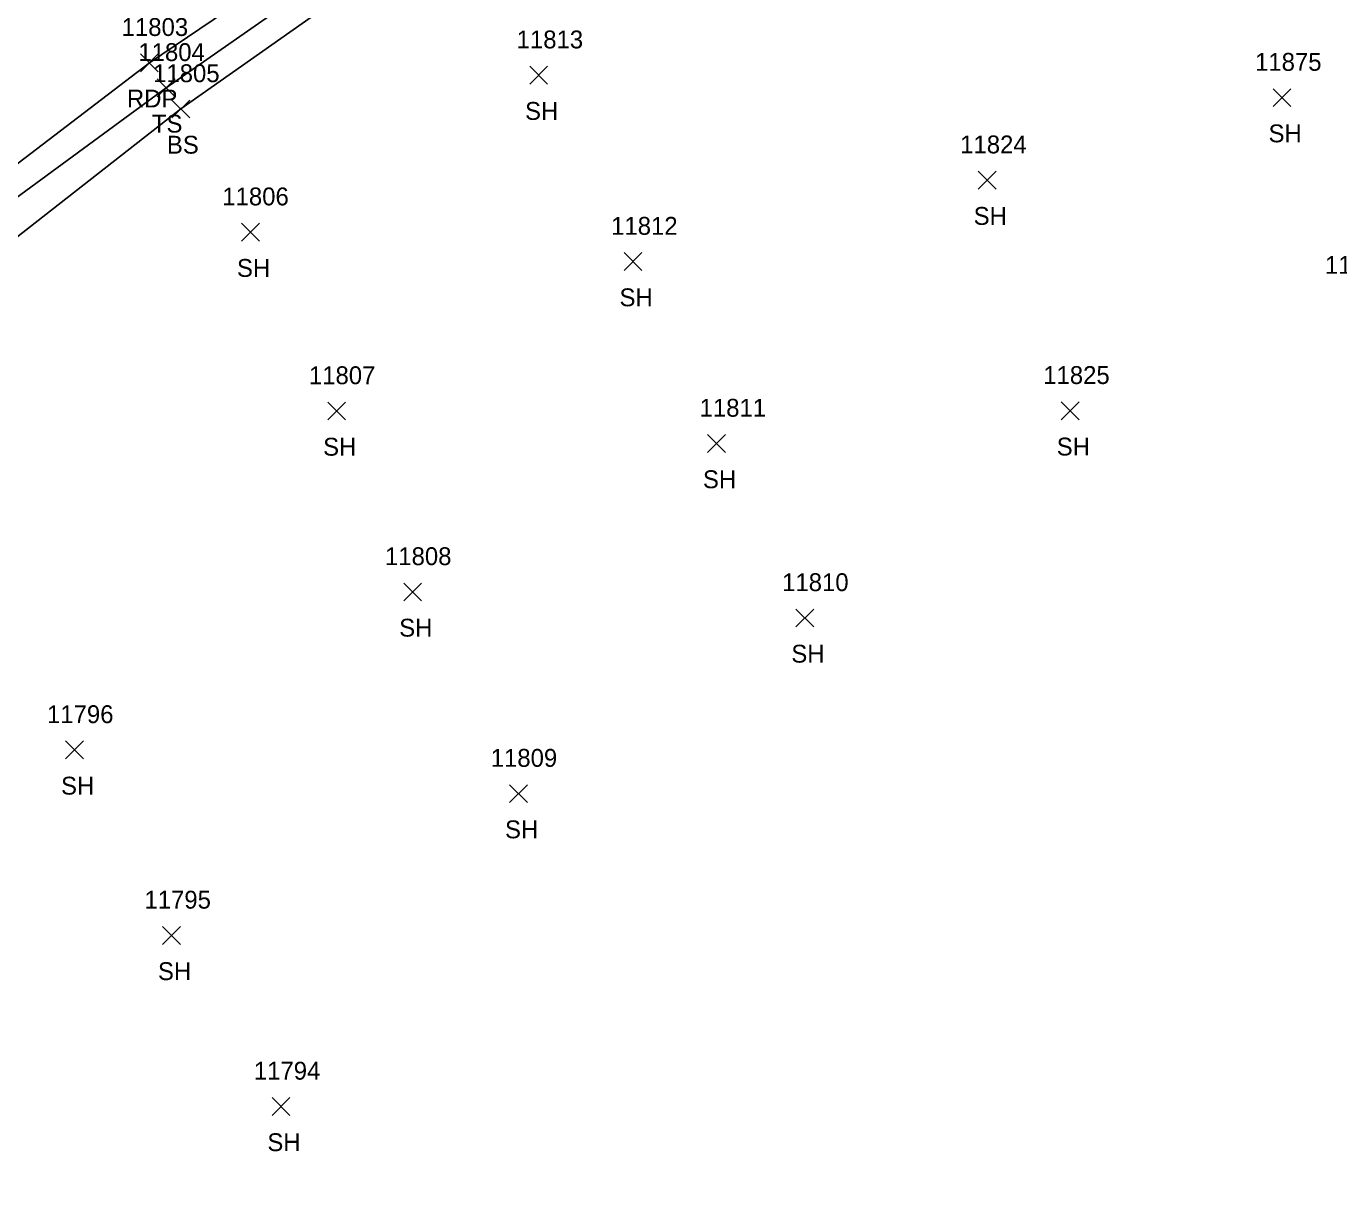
# Model space of a CAD drawing. Extents: x 1475671 to 1477951, y 592661 to 593821.
# Drawn here: x 1477117.1 to 1477263.9, y 593424.9 to 593555 of the extents above; entities that cross this region are included whole.
import ezdxf

# ---------------------------------------------------------------- set-up
doc = ezdxf.new("R2010")
doc.units = 0
for name, color, linetype in [('L_A', 7, 'Continuous'), ('L_I', 7, 'Continuous'), ('L_TIC', 7, 'Continuous'), ('LELB', 7, 'Continuous'), ('P_A', 7, 'Continuous'), ('P_I', 7, 'Continuous'), ('P_TIC', 7, 'Continuous'), ('PET', 7, 'Continuous')]:
    doc.layers.add(name, color=color, linetype=linetype)

msp = doc.modelspace()

# ---------------------------------------------------------------- linework, layer by layer
at = {"layer": 'L_TIC'}
for points in [[(1477173.41, 593548.57), (1477175.41, 593550.57)], [(1477175.41, 593548.57), (1477173.41, 593550.57)], [(1477131.73, 593547.15), (1477133.73, 593549.15)], [(1477133.73, 593547.15), (1477131.73, 593549.15)], [(1477256.58, 593546.06), (1477258.58, 593548.06)], [(1477258.58, 593546.06), (1477256.58, 593548.06)], [(1477133.38, 593544.79), (1477135.38, 593546.79)], [(1477135.38, 593544.79), (1477133.38, 593546.79)], [(1477223.59, 593536.82), (1477225.59, 593538.82)], [(1477225.59, 593536.82), (1477223.59, 593538.82)], [(1477141.17, 593531), (1477143.17, 593533)], [(1477143.17, 593531), (1477141.17, 593533)], [(1477183.97, 593527.71), (1477185.97, 593529.71)], [(1477185.97, 593527.71), (1477183.97, 593529.71)], [(1477150.82, 593510.99), (1477152.82, 593512.99)], [(1477152.82, 593510.99), (1477150.82, 593512.99)], [(1477232.88, 593511.01), (1477234.88, 593513.01)], [(1477234.88, 593511.01), (1477232.88, 593513.01)], [(1477193.31, 593507.35), (1477195.31, 593509.35)], [(1477195.31, 593507.35), (1477193.31, 593509.35)], [(1477159.32, 593490.74), (1477161.32, 593492.74)], [(1477161.32, 593490.74), (1477159.32, 593492.74)], [(1477203.2, 593487.83), (1477205.2, 593489.83)], [(1477205.2, 593487.83), (1477203.2, 593489.83)], [(1477121.49, 593473.06), (1477123.49, 593475.06)], [(1477123.49, 593473.06), (1477121.49, 593475.06)], [(1477171.16, 593468.17), (1477173.16, 593470.17)], [(1477173.16, 593468.17), (1477171.16, 593470.17)], [(1477132.33, 593452.3), (1477134.33, 593454.3)], [(1477134.33, 593452.3), (1477132.33, 593454.3)], [(1477144.58, 593433.16), (1477146.58, 593435.16)], [(1477146.58, 593433.16), (1477144.58, 593435.16)]]:
    msp.add_lwpolyline(points, dxfattribs=at)
at = {"layer": 'LELB'}
for points in [[(1477055.95, 593478.11), (1477074.78, 593497.41), (1477099.84, 593518.79), (1477134.38, 593545.79), (1477166.94, 593568.76), (1477207.75, 593594.56), (1477237.01, 593614.27), (1477256.43, 593624.24), (1477293.96, 593641.04), (1477304.8, 593646.41), (1477345.23, 593662.26), (1477383.56, 593674.31), (1477424.33, 593683.35), (1477474.43, 593689.99), (1477503.05, 593695.22), (1477531.19, 593697.25), (1477568.45, 593701.91)], [(1476970.32, 593415.97), (1476999.65, 593441.77), (1477011.08, 593451.76), (1477020.84, 593458.8), (1477029.39, 593465.42), (1477043.63, 593475.69), (1477052.67, 593482.42), (1477071.54, 593501.59), (1477097.81, 593522.54), (1477132.73, 593548.15), (1477165.81, 593571.26), (1477206.03, 593598.34), (1477236.29, 593616.29), (1477255.56, 593625.95), (1477292.71, 593644.19), (1477303.48, 593648.85), (1477344.61, 593663.93), (1477382.86, 593676.29), (1477423.58, 593686.25), (1477474.01, 593693.84)]]:
    msp.add_lwpolyline(points, dxfattribs=at)
at = {"layer": 'P_TIC'}
for points in [[(1477129.86, 593549.96), (1477131.86, 593551.96)], [(1477131.86, 593549.96), (1477129.86, 593551.96)]]:
    msp.add_lwpolyline(points, dxfattribs=at)
at = {"layer": 'PET'}
msp.add_lwpolyline([(1476967.73, 593418.7), (1476998.53, 593444.47), (1477010.16, 593454.71), (1477020.69, 593463.7), (1477040.87, 593480.17), (1477070.05, 593503.84), (1477096.22, 593524.5), (1477130.86, 593550.96), (1477164.87, 593573.97), (1477205.52, 593600.91), (1477235.56, 593618.03), (1477291.48, 593646.91), (1477343.59, 593667.49), (1477381.85, 593678.97), (1477423.34, 593689.19), (1477473.94, 593697.4)], dxfattribs=at)

# ---------------------------------------------------------------- texts
at = {"layer": 'L_A'}
for s, p in [('SH', (1477172.89, 593544.57)), ('TS', (1477131.14, 593543.15)), ('SH', (1477256.07, 593542.06)), ('BS', (1477132.82, 593540.79)), ('SH', (1477223.08, 593532.82)), ('SH', (1477140.66, 593527)), ('SH', (1477183.46, 593523.71)), ('SH', (1477150.3, 593506.99)), ('SH', (1477232.37, 593507.01)), ('SH', (1477192.79, 593503.35)), ('SH', (1477158.81, 593486.74)), ('SH', (1477202.68, 593483.83)), ('SH', (1477120.98, 593469.06)), ('SH', (1477170.65, 593464.17)), ('SH', (1477131.82, 593448.3)), ('SH', (1477144.06, 593429.16))]:
    msp.add_text(s, height=2, dxfattribs=at).set_placement(p)
at = {"layer": 'L_I'}
for s, p in [('11813', (1477171.95, 593552.57)), ('11804', (1477129.63, 593551.15)), ('11805', (1477131.28, 593548.79)), ('11875', (1477254.56, 593550.06)), ('11824', (1477221.57, 593540.82)), ('11806', (1477139.02, 593535)), ('11812', (1477182.52, 593531.71)), ('11878', (1477262.38, 593527.34)), ('11807', (1477148.71, 593514.99)), ('11825', (1477230.86, 593515.01)), ('11811', (1477192.42, 593511.35)), ('11808', (1477157.22, 593494.74)), ('11810', (1477201.65, 593491.83)), ('11796', (1477119.41, 593477.06)), ('11809', (1477169.05, 593472.17)), ('11795', (1477130.31, 593456.3)), ('11794', (1477142.55, 593437.16))]:
    msp.add_text(s, height=2, dxfattribs=at).set_placement(p)
at = {"layer": 'P_A'}
msp.add_text('RDP', height=2, dxfattribs=at).set_placement((1477128.35, 593545.96))
at = {"layer": 'P_I'}
msp.add_text('11803', height=2, dxfattribs=at).set_placement((1477127.76, 593553.96))

doc.saveas('drawing.dxf')
